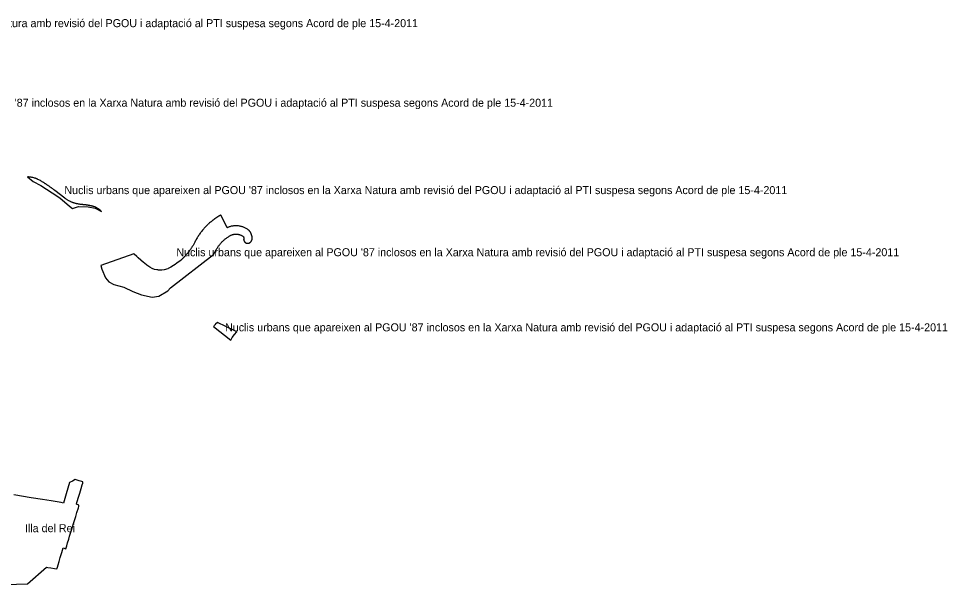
# Model space of a CAD drawing. Extents: x 599912 to 613490, y 4411003 to 4422920.
# Drawn here: x 610052 to 611443, y 4415868 to 4416716 of the extents above; entities that cross this region are included whole.
import ezdxf

# ---------------------------------------------------------------- set-up
doc = ezdxf.new("R2010")
doc.units = 0
doc.layers.add('Diligencia', color=7, linetype='Continuous')
doc.layers.add('Pla Especial', color=7, linetype='Continuous')

msp = doc.modelspace()

# ---------------------------------------------------------------- linework, layer by layer
at = {"layer": 'Diligencia'}
for points in [[(610091.6, 4416468.4), (610090.9, 4416468.8), (610090.3, 4416469.2), (610089.7, 4416469.7), (610089, 4416470.1), (610088.4, 4416470.5), (610087.8, 4416470.9), (610087.1, 4416471.3), (610086.5, 4416471.7), (610085.4, 4416472.4), (610085.3, 4416472.4), (610084.3, 4416473.1), (610084.2, 4416473.1), (610083.1, 4416473.7), (610083, 4416473.8), (610082.9, 4416473.8), (610081.8, 4416474.3), (610081.8, 4416474.4), (610080.6, 4416474.9), (610080.5, 4416474.9), (610079.4, 4416475.5), (610079.3, 4416475.5), (610078.1, 4416475.9), (610078, 4416476), (610076.9, 4416476.4), (610076.8, 4416476.4), (610076.7, 4416476.5), (610075.5, 4416476.8), (610075.5, 4416476.8), (610074.2, 4416477.2), (610074.2, 4416477.2), (610072.9, 4416477.5), (610072.9, 4416477.5), (610072.8, 4416477.6), (610071.7, 4416477.8), (610071.5, 4416477.8), (610070.3, 4416478), (610070.2, 4416478.1), (610070.1, 4416478.1), (610068.9, 4416478.3), (610067.6, 4416478.4), (610067.5, 4416478.4), (610066.2, 4416478.5), (610066.2, 4416478.5), (610066.1, 4416478.5), (610064.9, 4416478.6), (610064.8, 4416478.6), (610064.7, 4416478.6), (610073.5, 4416471.7), (610084.8, 4416465.8), (610102, 4416454.5), (610113.4, 4416447.1), (610128, 4416434.6), (610132.4, 4416431.1), (610141.3, 4416434.2), (610156, 4416433.6), (610166.5, 4416431.9), (610175.6, 4416426.9), (610175.5, 4416427), (610174.9, 4416427.6), (610174.8, 4416427.6), (610173.7, 4416428.6), (610173.6, 4416428.6), (610172.4, 4416429.6), (610172.4, 4416429.6), (610171.1, 4416430.5), (610171.1, 4416430.5), (610169.8, 4416431.4), (610169.8, 4416431.4), (610168.4, 4416432.2), (610168.4, 4416432.2), (610168.4, 4416432.2), (610167, 4416433), (610167, 4416433), (610165.6, 4416433.7), (610165, 4416433.9), (610164.4, 4416434), (610163.8, 4416434.2), (610163.2, 4416434.4), (610162.6, 4416434.5), (610162, 4416434.7), (610161.4, 4416434.8), (610160.8, 4416435), (610160.2, 4416435.1), (610159.6, 4416435.3), (610159, 4416435.4), (610158.3, 4416435.5), (610157.7, 4416435.6), (610157.1, 4416435.8), (610156.5, 4416435.9), (610155.9, 4416436), (610155.3, 4416436.1), (610154.6, 4416436.2), (610154, 4416436.3), (610153.4, 4416436.4), (610152.8, 4416436.5), (610152.2, 4416436.5), (610151.5, 4416436.6), (610150.9, 4416436.7), (610150.3, 4416436.7), (610149.7, 4416436.8), (610149.1, 4416436.9), (610148.4, 4416436.9), (610147.8, 4416437), (610147.2, 4416437), (610146.6, 4416437.1), (610145.7, 4416437.1), (610144.8, 4416437.2), (610143.9, 4416437.3), (610143, 4416437.5), (610142.1, 4416437.6), (610141.2, 4416437.8), (610140.3, 4416438), (610139.5, 4416438.2), (610138.6, 4416438.4), (610137.7, 4416438.6), (610136.9, 4416438.8), (610136, 4416439.1), (610135.8, 4416439.1), (610135.1, 4416439.3), (610134.3, 4416439.6), (610133.4, 4416439.9), (610132.6, 4416440.2), (610131.8, 4416440.6), (610130.9, 4416440.9), (610130.1, 4416441.3), (610129.3, 4416441.6), (610128.5, 4416442), (610127.7, 4416442.4), (610126.9, 4416442.8), (610126.1, 4416443.2), (610125.3, 4416443.7), (610124.5, 4416444.1), (610123.8, 4416444.6), (610123, 4416445.1), (610122.4, 4416445.5), (610122.2, 4416445.6), (610121.5, 4416446.1), (610120.8, 4416446.6), (610105.9, 4416458.4), (610105.8, 4416458.5), (610105.2, 4416458.9), (610104.6, 4416459.4), (610104, 4416459.8), (610103.4, 4416460.2), (610102.7, 4416460.7), (610102.1, 4416461.1), (610101.5, 4416461.6), (610100.9, 4416462), (610100.3, 4416462.4), (610099.7, 4416462.9), (610099, 4416463.3), (610098.4, 4416463.7), (610097.8, 4416464.2), (610097.2, 4416464.6), (610096.6, 4416465), (610095.9, 4416465.5), (610095.3, 4416465.9), (610094.7, 4416466.3), (610094.1, 4416466.7), (610093.4, 4416467.2), (610092.8, 4416467.6), (610092.2, 4416468)], [(610344.7, 4416363.8), (610344.7, 4416363.9), (610344.7, 4416363.9), (610344.8, 4416364), (610344.8, 4416364.1), (610344.8, 4416364.2), (610344.9, 4416364.3), (610344.9, 4416364.3), (610345, 4416364.4), (610345, 4416364.5), (610345.1, 4416364.6), (610345.1, 4416364.7), (610345.6, 4416365.7), (610346.1, 4416366.7), (610346.6, 4416367.6), (610347.1, 4416368.6), (610347.7, 4416369.6), (610348.3, 4416370.5), (610348.8, 4416371.5), (610349.5, 4416372.4), (610350.1, 4416373.3), (610350.7, 4416374.3), (610351.4, 4416375.2), (610352.1, 4416376), (610352.7, 4416376.9), (610353.5, 4416377.8), (610354.2, 4416378.6), (610354.9, 4416379.5), (610355.7, 4416380.3), (610356.4, 4416381.1), (610357.2, 4416381.9), (610358, 4416382.6), (610358.9, 4416383.4), (610359.7, 4416384.1), (610360.5, 4416384.9), (610361.4, 4416385.6), (610362.3, 4416386.3), (610363.1, 4416387), (610364, 4416387.6), (610364.9, 4416388.3), (610365.9, 4416388.9), (610366.8, 4416389.5), (610367.7, 4416390.1), (610368.3, 4416390.5), (610369, 4416390.8), (610369.6, 4416391.1), (610370.2, 4416391.4), (610370.9, 4416391.6), (610371.5, 4416391.9), (610372.2, 4416392.1), (610372.9, 4416392.3), (610373.5, 4416392.4), (610374.2, 4416392.6), (610374.9, 4416392.7), (610375.6, 4416392.8), (610376.3, 4416392.8), (610377, 4416392.8), (610377.7, 4416392.9), (610378.4, 4416392.8), (610379.1, 4416392.8), (610379.8, 4416392.7), (610380.5, 4416392.6), (610381.2, 4416392.5), (610381.8, 4416392.3), (610382.5, 4416392.1), (610383.2, 4416391.9), (610383.8, 4416391.7), (610384.5, 4416391.4), (610385.1, 4416391.1), (610385.8, 4416390.8), (610386.4, 4416390.5), (610387, 4416390.2), (610387.6, 4416389.8), (610388.1, 4416389.4), (610388.2, 4416389.4), (610388.2, 4416389.3), (610388.2, 4416389.3), (610388.3, 4416389.2), (610388.3, 4416389.2), (610388.3, 4416389.1), (610388.3, 4416389.1), (610388.4, 4416389.1), (610388.4, 4416389), (610388.4, 4416389), (610388.5, 4416388.9), (610388.5, 4416388.9), (610388.5, 4416388.8), (610388.6, 4416388.8), (610388.6, 4416388.7), (610388.6, 4416388.7), (610388.6, 4416388.6), (610388.6, 4416388.6), (610388.7, 4416388.5), (610388.7, 4416388.5), (610388.7, 4416388.4), (610388.7, 4416388.4), (610388.8, 4416388.3), (610388.8, 4416388.3), (610388.8, 4416388.2), (610388.8, 4416388.1), (610388.8, 4416388.1), (610388.8, 4416388.1), (610388.9, 4416388), (610388.9, 4416388), (610388.9, 4416387.9), (610388.9, 4416387.9), (610388.9, 4416387.8), (610388.9, 4416387.8), (610388.9, 4416387.7), (610388.9, 4416387.7), (610389, 4416387.6), (610389, 4416387.6), (610389, 4416387.5), (610389, 4416387.5), (610389, 4416387.4), (610389, 4416387.4), (610389, 4416387.3), (610389, 4416387.2), (610389, 4416387.2), (610389, 4416387.1), (610389, 4416387.1), (610389, 4416387), (610389, 4416387), (610389, 4416386.9), (610389, 4416386.8), (610389, 4416386.8), (610389, 4416386.7), (610389, 4416386.7), (610389, 4416386.6), (610389, 4416386.6), (610389, 4416386.5), (610389, 4416386.5), (610389, 4416386.4), (610389, 4416386.3), (610388.9, 4416386.2), (610388.9, 4416386.1), (610388.9, 4416386), (610388.9, 4416385.9), (610388.9, 4416385.8), (610388.9, 4416385.5), (610388.8, 4416385.4), (610388.8, 4416385.3), (610388.8, 4416385.1), (610388.8, 4416385), (610388.8, 4416384.8), (610388.9, 4416384.6), (610388.9, 4416384.5), (610388.9, 4416384.4), (610388.9, 4416384.1), (610388.9, 4416384), (610389, 4416383.9), (610389, 4416383.6), (610389.1, 4416383.5), (610389.1, 4416383.4), (610389.2, 4416383.2), (610389.2, 4416383.1), (610389.2, 4416383), (610389.3, 4416382.7), (610389.4, 4416382.6), (610389.4, 4416382.5), (610389.5, 4416382.3), (610389.6, 4416382.2), (610389.7, 4416382.1), (610389.8, 4416381.9), (610389.9, 4416381.8), (610389.9, 4416381.7), (610390.1, 4416381.5), (610390.1, 4416381.4), (610390.2, 4416381.3), (610390.4, 4416381.1), (610390.5, 4416381), (610390.5, 4416381), (610390.7, 4416380.8), (610390.8, 4416380.7), (610390.9, 4416380.6), (610391.1, 4416380.5), (610391.2, 4416380.4), (610391.2, 4416380.3), (610391.4, 4416380.2), (610391.6, 4416380.1), (610391.6, 4416380), (610391.8, 4416380), (610391.9, 4416379.9), (610392, 4416379.8), (610392.1, 4416379.8), (610392.3, 4416379.7), (610392.4, 4416379.6), (610392.5, 4416379.6), (610392.7, 4416379.5), (610392.9, 4416379.5), (610392.9, 4416379.4), (610393.2, 4416379.4), (610393.4, 4416379.3), (610393.4, 4416379.3), (610393.6, 4416379.3), (610393.8, 4416379.2), (610393.9, 4416379.2), (610394.1, 4416379.2), (610394.3, 4416379.2), (610394.3, 4416379.1), (610394.6, 4416379.1), (610394.8, 4416379.1), (610394.8, 4416379.1), (610395.1, 4416379.1), (610395.3, 4416379.1), (610395.3, 4416379.1), (610395.6, 4416379.2), (610395.8, 4416379.2), (610395.8, 4416379.2), (610396, 4416379.3), (610396.2, 4416379.3), (610396.3, 4416379.3), (610396.5, 4416379.4), (610396.7, 4416379.4), (610396.7, 4416379.4), (610397, 4416379.5), (610397.1, 4416379.6), (610397.2, 4416379.6), (610397.6, 4416379.8), (610397.6, 4416379.8), (610398, 4416380), (610398, 4416380), (610398.4, 4416380.3), (610398.4, 4416380.3), (610398.8, 4416380.6), (610398.9, 4416380.7), (610399, 4416380.8), (610399.1, 4416380.9), (610399.3, 4416381), (610399.4, 4416381.1), (610399.5, 4416381.2), (610399.6, 4416381.3), (610399.7, 4416381.4), (610399.8, 4416381.5), (610399.9, 4416381.7), (610400, 4416381.8), (610400.1, 4416381.9), (610400.2, 4416382), (610400.3, 4416382.1), (610400.3, 4416382.3), (610400.4, 4416382.4), (610400.5, 4416382.5), (610400.6, 4416382.7), (610400.7, 4416382.8), (610400.7, 4416382.9), (610400.8, 4416383.1), (610400.9, 4416383.2), (610400.9, 4416383.3), (610401, 4416383.5), (610401, 4416383.6), (610401.1, 4416383.8), (610401.1, 4416383.9), (610401.2, 4416384.1), (610401.2, 4416384.2), (610401.3, 4416384.4), (610401.3, 4416384.5), (610401.4, 4416385), (610401.4, 4416385.5), (610401.5, 4416386), (610401.5, 4416386.5), (610401.5, 4416387), (610401.5, 4416387.5), (610401.4, 4416388), (610401.4, 4416388.6), (610401.4, 4416388.8), (610401.4, 4416389.1), (610401.3, 4416389.6), (610401.2, 4416390.1), (610401.1, 4416390.6), (610401, 4416391), (610400.8, 4416391.5), (610400.7, 4416392), (610400.5, 4416392.5), (610400.3, 4416393), (610400.2, 4416393.4), (610399.9, 4416393.9), (610399.7, 4416394.4), (610399.5, 4416394.8), (610399.2, 4416395.3), (610399, 4416395.7), (610398.7, 4416396.1), (610398.4, 4416396.5), (610398.1, 4416396.9), (610397.8, 4416397.3), (610397.5, 4416397.7), (610397.1, 4416398.1), (610396.8, 4416398.5), (610396.4, 4416398.8), (610395.5, 4416399.5), (610395.2, 4416399.7), (610394.6, 4416400.1), (610393.7, 4416400.7), (610392.7, 4416401.3), (610391.8, 4416401.8), (610390.8, 4416402.3), (610389.8, 4416402.8), (610388.8, 4416403.2), (610387.7, 4416403.6), (610386.7, 4416404), (610385.6, 4416404.3), (610384.6, 4416404.5), (610383.5, 4416404.8), (610382.4, 4416405), (610381.3, 4416405.1), (610380.2, 4416405.3), (610379.1, 4416405.3), (610378, 4416405.4), (610376.9, 4416405.4), (610375.8, 4416405.3), (610374.7, 4416405.3), (610373.6, 4416405.2), (610372.5, 4416405), (610371.4, 4416404.8), (610370.3, 4416404.6), (610369.2, 4416404.3), (610368.2, 4416404), (610367.1, 4416403.6), (610366.1, 4416403.2), (610365.1, 4416402.8), (610364.7, 4416402.7), (610364.4, 4416402.5), (610364.1, 4416402.4), (610355, 4416420.5), (610354.6, 4416421.1), (610354.5, 4416421.1), (610354.3, 4416421), (610354.2, 4416420.9), (610354, 4416420.9), (610353.9, 4416420.8), (610353.7, 4416420.7), (610353.6, 4416420.7), (610353.4, 4416420.6), (610353.3, 4416420.5), (610353.1, 4416420.4), (610353, 4416420.4), (610352.8, 4416420.3), (610352.7, 4416420.2), (610352.5, 4416420.1), (610352.4, 4416420.1), (610352.2, 4416420), (610352.1, 4416419.9), (610351.9, 4416419.8), (610351.8, 4416419.7), (610351.7, 4416419.7), (610351.5, 4416419.6), (610351.4, 4416419.5), (610351.2, 4416419.4), (610351.1, 4416419.3), (610350.9, 4416419.2), (610350.8, 4416419.1), (610350.7, 4416419.1), (610350.5, 4416419), (610350.4, 4416418.9), (610350.2, 4416418.8), (610350.1, 4416418.7), (610349.8, 4416418.5), (610349.6, 4416418.4), (610349.3, 4416418.2), (610349, 4416418), (610348.8, 4416417.9), (610348.5, 4416417.7), (610348.3, 4416417.5), (610348, 4416417.4), (610347.8, 4416417.2), (610347.5, 4416417), (610347.2, 4416416.9), (610347, 4416416.7), (610346.7, 4416416.5), (610346.5, 4416416.3), (610346.2, 4416416.2), (610346, 4416416), (610345.7, 4416415.8), (610345.5, 4416415.6), (610345.2, 4416415.5), (610345, 4416415.3), (610344.7, 4416415.1), (610344.5, 4416414.9), (610344.2, 4416414.7), (610344, 4416414.6), (610343.7, 4416414.4), (610343.5, 4416414.2), (610343.2, 4416414), (610343, 4416413.8), (610342.7, 4416413.6), (610342.5, 4416413.4), (610342.2, 4416413.3), (610341.1, 4416412.4), (610340, 4416411.5), (610339, 4416410.6), (610337.9, 4416409.7), (610336.9, 4416408.8), (610336, 4416408), (610335.8, 4416407.8), (610334.8, 4416406.9), (610333.8, 4416405.9), (610332.8, 4416404.9), (610331.8, 4416403.9), (610330.8, 4416402.8), (610329.9, 4416401.8), (610329, 4416400.8), (610328.1, 4416399.7), (610327.2, 4416398.6), (610326.3, 4416397.5), (610325.4, 4416396.4), (610324.6, 4416395.3), (610323.7, 4416394.2), (610323.7, 4416394.2), (610322.9, 4416393), (610322.1, 4416391.9), (610321.3, 4416390.7), (610320.6, 4416389.5), (610319.8, 4416388.3), (610319.1, 4416387.1), (610318.4, 4416385.9), (610317.7, 4416384.7), (610317, 4416383.5), (610316.4, 4416382.2), (610315.7, 4416381), (610315.6, 4416380.8), (610315.1, 4416379.7), (610314.6, 4416378.8), (610314.1, 4416377.9), (610313.5, 4416376.9), (610313, 4416376), (610312.5, 4416375.1), (610311.9, 4416374.2), (610311.3, 4416373.4), (610310.7, 4416372.5), (610310.2, 4416371.6), (610309.6, 4416370.7), (610309, 4416369.9), (610308.4, 4416369), (610307.9, 4416368.4), (610307.7, 4416368.2), (610307.1, 4416367.3), (610306.5, 4416366.5), (610305.8, 4416365.6), (610305.2, 4416364.8), (610304.5, 4416364), (610303.8, 4416363.2), (610303.2, 4416362.4), (610302.5, 4416361.6), (610301.8, 4416360.8), (610301.1, 4416360), (610300.4, 4416359.2), (610299.6, 4416358.4), (610299.1, 4416357.9), (610298.9, 4416357.7), (610298.2, 4416356.9), (610297.4, 4416356.2), (610296.7, 4416355.4), (610295.9, 4416354.7), (610295.2, 4416354), (610288.7, 4416349.2), (610286.1, 4416347.3), (610283.5, 4416345.8), (610279.6, 4416343.5), (610275.5, 4416341.1), (610275.3, 4416341), (610269.8, 4416339.5), (610266.1, 4416338.9), (610261.5, 4416338.8), (610260.2, 4416339.1), (610260.2, 4416339.1), (610258.9, 4416339.3), (610255.3, 4416339.9), (610252, 4416341.2), (610248.2, 4416343.2), (610248.1, 4416343.2), (610243.6, 4416346.4), (610240.3, 4416349.1), (610238.6, 4416350.4), (610230.8, 4416357.3), (610228.8, 4416359.1), (610224.7, 4416362.8), (610224.1, 4416363.4), (610174.6, 4416345.7), (610174.6, 4416345.7), (610176.1, 4416340.1), (610181.9, 4416327.5), (610186.6, 4416321.5), (610194.5, 4416317.2), (610209.3, 4416313.3), (610222.7, 4416307), (610235.7, 4416302), (610252, 4416298.3), (610261.6, 4416299.9), (610275.2, 4416308), (610279.1, 4416312.4), (610343.8, 4416362.2)], [(610343.5, 4416254.2), (610369.4, 4416234.2), (610371.6, 4416237.9), (610374.9, 4416242.5), (610378.5, 4416246.7), (610375.7, 4416248), (610374.8, 4416248.5), (610374.8, 4416248.5), (610349.5, 4416260.3), (610346.8, 4416257.7), (610346.1, 4416257), (610345.9, 4416256.9), (610345.2, 4416256.1), (610344, 4416254.8)]]:
    msp.add_lwpolyline(points, close=True, dxfattribs=at)
at = {"layer": 'Pla Especial'}
msp.add_lwpolyline([(610032.2, 4415868), (610065, 4415869), (610093.5, 4415893.9), (610095.5, 4415893.5), (610099.9, 4415892.7), (610105.6, 4415891.7), (610108.9, 4415891.2), (610109.7, 4415893.8), (610110.7, 4415897.2), (610112.3, 4415902.3), (610114.1, 4415908.6), (610116.4, 4415915.9), (610118.4, 4415922.7), (610122.4, 4415921.4), (610123.8, 4415926), (610125.1, 4415930.2), (610126.8, 4415935.6), (610128.1, 4415940.1), (610130.9, 4415949.3), (610133.9, 4415959.1), (610137.2, 4415969.6), (610139.1, 4415975.9), (610141.2, 4415982.7), (610141.7, 4415984.6), (610142.1, 4415987), (610138.4, 4415988.5), (610139.1, 4415991), (610140.1, 4415994), (610141.1, 4415997.5), (610143.4, 4416005), (610145.4, 4416011.9), (610147, 4416017), (610147.8, 4416019.8), (610148, 4416021.8), (610146.4, 4416022.3), (610142.5, 4416023.3), (610136.5, 4416025), (610132.4, 4416022.7), (610128.1, 4416020.6), (610123.1, 4416003.7), (610119, 4415989.8), (610115.4, 4415990.6), (610100.2, 4415993.1), (610087.5, 4415995.2), (610070.5, 4415998), (610044.3, 4416002.3)], dxfattribs=at)

# ---------------------------------------------------------------- texts
at = {"layer": 'Diligencia'}
for p in [(609566.9, 4416702.9), (609769.2, 4416583.7), (610120.2, 4416452.8), (610288, 4416359.7), (610361, 4416247.2)]:
    msp.add_text("Nuclis urbans que apareixen al PGOU '87 inclosos en la Xarxa Natura amb revisió del PGOU i adaptació al PTI suspesa segons Acord de ple 15-4-2011", height=12, dxfattribs=at).set_placement(p)
at = {"layer": 'Pla Especial'}
msp.add_text('Illa del Rei', height=12, dxfattribs=at).set_placement((610061.1, 4415946.3))

doc.saveas('drawing.dxf')
